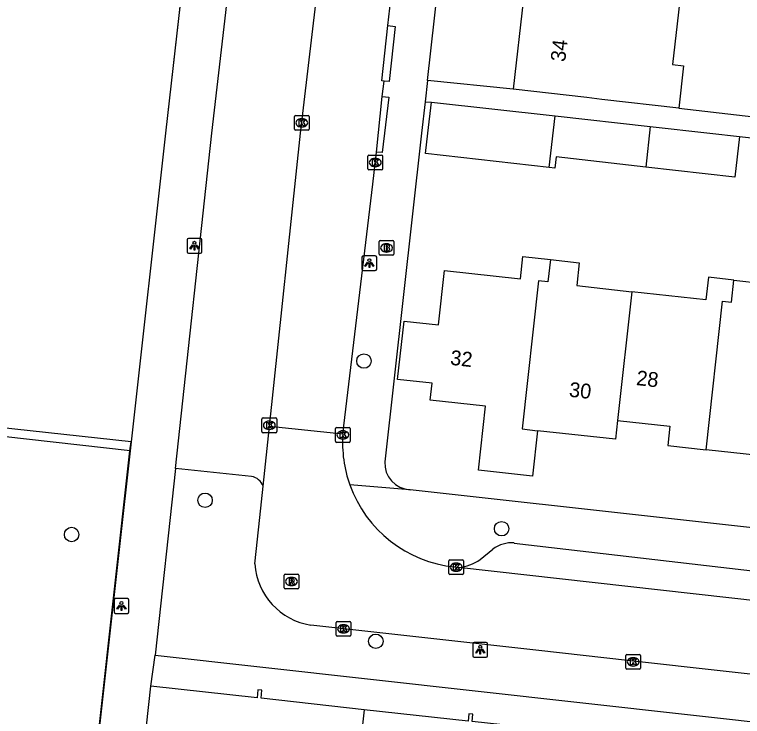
# Model space of a CAD drawing. Extents: x 162082 to 163393, y 388091 to 388632.
# Drawn here: x 162700.61 to 162749.8, y 388210.56 to 388258.01 of the extents above; entities that cross this region are included whole.
import ezdxf

# ---------------------------------------------------------------- set-up
doc = ezdxf.new("R2010")
doc.units = 0
for name, color, linetype in [('IMGEO_Boom', 7, 'Continuous'), ('IMGEO_Brandkraan', 7, 'Continuous'), ('IMGEO_Groenvoorziening', 7, 'Continuous'), ('IMGEO_Hek', 7, 'Continuous'), ('IMGEO_Kolk', 7, 'Continuous'), ('IMGEO_Lichtpunt', 7, 'Continuous'), ('IMGEO_Pand', 7, 'Continuous'), ('IMGEO_Pand_nummerreeks', 7, 'Continuous'), ('IMGEO_Rijbaan_lokaal_open', 7, 'Continuous'), ('IMGEO_Rioolput', 7, 'Continuous'), ('IMGEO_Voetpad_open', 7, 'Continuous')]:
    doc.layers.add(name, color=color, linetype=linetype)

msp = doc.modelspace()

# ---------------------------------------------------------------- linework, layer by layer
at = {"layer": 'IMGEO_Boom'}
for centre in [(162724.221, 388234.588), (162713.487, 388225.175), (162704.464, 388222.861), (162733.523, 388223.253), (162725.022, 388215.647)]:
    msp.add_circle(centre, 0.489, dxfattribs=at)
at = {"layer": 'IMGEO_Brandkraan'}
for p, q in [((162725.247, 388241.81), (162725.247, 388242.662)), ((162725.322, 388242.736), (162726.174, 388242.736)), ((162725.735, 388242.516), (162725.76, 388242.516)), ((162726.248, 388242.662), (162726.248, 388241.81)), ((162726.174, 388241.736), (162725.322, 388241.736)), ((162725.758, 388241.956), (162725.733, 388241.956))]:
    msp.add_line(p, q, dxfattribs=at)
for points in [[(162725.247, 388241.81), (162725.247, 388242.662)], [(162725.322, 388242.736), (162726.174, 388242.736)], [(162726.248, 388242.662), (162726.248, 388241.81)], [(162725.595, 388242.436), (162725.595, 388242.036), (162725.808, 388242.036)], [(162725.826, 388242.436), (162725.595, 388242.436)], [(162725.774, 388242.355), (162725.72, 388242.355), (162725.72, 388242.279)], [(162725.72, 388242.279), (162725.773, 388242.279)], [(162725.782, 388242.203), (162725.72, 388242.203), (162725.72, 388242.122)], [(162725.72, 388242.122), (162725.782, 388242.122)], [(162726.174, 388241.736), (162725.322, 388241.736)]]:
    msp.add_lwpolyline(points, dxfattribs=at)
for centre, radius, start, end in [((162725.324, 388242.66), 0.0765, 91.552, 178.448), ((162725.324, 388242.66), 0.0765, 91.552, 178.448), ((162726.172, 388242.66), 0.0765, 1.552, 88.448), ((162726.172, 388242.66), 0.0765, 1.552, 88.448), ((162725.775, 388242.317), 0.0379, 267.8285, 90.9355), ((162725.783, 388242.162), 0.0404, 269.8759, 90.5077), ((162725.814, 388242.287), 0.251, 268.6676, 293.5347), ((162725.83, 388242.291), 0.145, 59.4692, 91.5367), ((162725.855, 388242.338), 0.0922, 285.5137, 58.1501), ((162725.86, 388242.146), 0.105, 301.3115, 78.989), ((162725.324, 388241.812), 0.0765, 181.552, 268.448), ((162725.324, 388241.812), 0.0765, 181.552, 268.448), ((162726.172, 388241.812), 0.0765, 271.552, 358.448), ((162726.172, 388241.812), 0.0765, 271.552, 358.448)]:
    msp.add_arc(centre, radius, start, end, dxfattribs=at)
for centre, major_axis, ratio, start_param, end_param in [((162725.734, 388242.236), (-0.387, 0.002), 0.722429, 4.712389, 7.853982), ((162725.759, 388242.236), (-0.39, 0.002), 0.717154, 1.570796, 4.712389)]:
    msp.add_ellipse(centre, major_axis=major_axis, ratio=ratio, start_param=start_param, end_param=end_param, dxfattribs=at)
at = {"layer": 'IMGEO_Groenvoorziening'}
msp.add_lwpolyline([(162708.484, 388229.124), (162656.335, 388234.801), (162656.279, 388234.387)], dxfattribs=at)
at = {"layer": 'IMGEO_Hek'}
for points in [[(162714.001, 388278.243), (162710.804, 388250), (162708.484, 388229.124), (162704.239, 388190.917)], [(162708.417, 388228.516), (162663.577, 388233.565), (162656.279, 388234.387), (162655.072, 388234.523), (162654.187, 388234.622)]]:
    msp.add_lwpolyline(points, dxfattribs=at)
at = {"layer": 'IMGEO_Kolk'}
for p, q in [((162719.518, 388250.268), (162719.518, 388251.12)), ((162719.593, 388251.194), (162720.445, 388251.194)), ((162720.006, 388250.974), (162720.031, 388250.974)), ((162720.519, 388251.12), (162720.519, 388250.268)), ((162720.029, 388250.414), (162720.004, 388250.414)), ((162720.445, 388250.194), (162719.593, 388250.194)), ((162724.486, 388247.585), (162724.486, 388248.437)), ((162724.561, 388248.511), (162725.413, 388248.511)), ((162725.487, 388248.437), (162725.487, 388247.585)), ((162724.974, 388248.291), (162724.999, 388248.291)), ((162725.413, 388247.511), (162724.561, 388247.511)), ((162724.997, 388247.731), (162724.972, 388247.731)), ((162717.403, 388230.743), (162718.255, 388230.743)), ((162717.328, 388229.817), (162717.328, 388230.669)), ((162717.816, 388230.523), (162717.841, 388230.523)), ((162718.329, 388230.669), (162718.329, 388229.817)), ((162718.255, 388229.743), (162717.403, 388229.743)), ((162717.839, 388229.963), (162717.814, 388229.963)), ((162722.295, 388229.166), (162722.295, 388230.018)), ((162722.37, 388230.092), (162723.222, 388230.092)), ((162722.783, 388229.872), (162722.808, 388229.872)), ((162723.296, 388230.018), (162723.296, 388229.166)), ((162722.806, 388229.312), (162722.781, 388229.312)), ((162723.222, 388229.092), (162722.37, 388229.092)), ((162729.958, 388220.229), (162729.958, 388221.081)), ((162730.033, 388221.155), (162730.885, 388221.155)), ((162730.446, 388220.935), (162730.471, 388220.935)), ((162730.959, 388221.081), (162730.959, 388220.229)), ((162730.469, 388220.375), (162730.444, 388220.375)), ((162730.885, 388220.155), (162730.033, 388220.155)), ((162722.345, 388216.061), (162722.345, 388216.913)), ((162722.42, 388216.987), (162723.272, 388216.987)), ((162723.346, 388216.913), (162723.346, 388216.061)), ((162722.833, 388216.767), (162722.858, 388216.767)), ((162723.272, 388215.987), (162722.42, 388215.987)), ((162722.856, 388216.207), (162722.831, 388216.207)), ((162741.917, 388213.824), (162741.917, 388214.676)), ((162741.992, 388214.75), (162742.844, 388214.75)), ((162742.405, 388214.53), (162742.43, 388214.53)), ((162742.918, 388214.676), (162742.918, 388213.824)), ((162742.428, 388213.97), (162742.403, 388213.97)), ((162742.844, 388213.75), (162741.992, 388213.75))]:
    msp.add_line(p, q, dxfattribs=at)
for points in [[(162719.518, 388250.268), (162719.518, 388251.12)], [(162719.593, 388251.194), (162720.445, 388251.194)], [(162719.839, 388250.894), (162719.962, 388250.894), (162719.962, 388250.743), (162720.092, 388250.894), (162720.256, 388250.894), (162720.11, 388250.743), (162720.263, 388250.494), (162720.111, 388250.494), (162720.026, 388250.658), (162719.962, 388250.591), (162719.962, 388250.494), (162719.839, 388250.494), (162719.839, 388250.894)], [(162720.519, 388251.12), (162720.519, 388250.268)], [(162720.445, 388250.194), (162719.593, 388250.194)], [(162724.486, 388247.585), (162724.486, 388248.437)], [(162724.561, 388248.511), (162725.413, 388248.511)], [(162725.487, 388248.437), (162725.487, 388247.585)], [(162724.807, 388248.211), (162724.93, 388248.211), (162724.93, 388248.06), (162725.06, 388248.211), (162725.224, 388248.211), (162725.078, 388248.06), (162725.231, 388247.811), (162725.079, 388247.811), (162724.994, 388247.975), (162724.93, 388247.908), (162724.93, 388247.811), (162724.807, 388247.811), (162724.807, 388248.211)], [(162725.413, 388247.511), (162724.561, 388247.511)], [(162717.403, 388230.743), (162718.255, 388230.743)], [(162717.328, 388229.817), (162717.328, 388230.669)], [(162717.649, 388230.443), (162717.772, 388230.443), (162717.772, 388230.292), (162717.902, 388230.443), (162718.066, 388230.443), (162717.92, 388230.292), (162718.073, 388230.043), (162717.921, 388230.043), (162717.836, 388230.207), (162717.772, 388230.14), (162717.772, 388230.043), (162717.649, 388230.043), (162717.649, 388230.443)], [(162718.329, 388230.669), (162718.329, 388229.817)], [(162718.255, 388229.743), (162717.403, 388229.743)], [(162722.295, 388229.166), (162722.295, 388230.018)], [(162722.37, 388230.092), (162723.222, 388230.092)], [(162722.616, 388229.792), (162722.739, 388229.792), (162722.739, 388229.641), (162722.869, 388229.792), (162723.033, 388229.792), (162722.887, 388229.641), (162723.04, 388229.392), (162722.888, 388229.392), (162722.803, 388229.556), (162722.739, 388229.489), (162722.739, 388229.392), (162722.616, 388229.392), (162722.616, 388229.792)], [(162723.296, 388230.018), (162723.296, 388229.166)], [(162723.222, 388229.092), (162722.37, 388229.092)], [(162729.958, 388220.229), (162729.958, 388221.081)], [(162730.033, 388221.155), (162730.885, 388221.155)], [(162730.279, 388220.855), (162730.402, 388220.855), (162730.402, 388220.704), (162730.532, 388220.855), (162730.696, 388220.855), (162730.55, 388220.704), (162730.703, 388220.455), (162730.551, 388220.455), (162730.466, 388220.619), (162730.402, 388220.552), (162730.402, 388220.455), (162730.279, 388220.455), (162730.279, 388220.855)], [(162730.959, 388221.081), (162730.959, 388220.229)], [(162730.885, 388220.155), (162730.033, 388220.155)], [(162722.345, 388216.061), (162722.345, 388216.913)], [(162722.42, 388216.987), (162723.272, 388216.987)], [(162723.346, 388216.913), (162723.346, 388216.061)], [(162722.666, 388216.687), (162722.789, 388216.687), (162722.789, 388216.536), (162722.919, 388216.687), (162723.083, 388216.687), (162722.937, 388216.536), (162723.09, 388216.287), (162722.938, 388216.287), (162722.853, 388216.451), (162722.789, 388216.384), (162722.789, 388216.287), (162722.666, 388216.287), (162722.666, 388216.687)], [(162723.272, 388215.987), (162722.42, 388215.987)], [(162741.917, 388213.824), (162741.917, 388214.676)], [(162741.992, 388214.75), (162742.844, 388214.75)], [(162742.238, 388214.45), (162742.361, 388214.45), (162742.361, 388214.299), (162742.491, 388214.45), (162742.655, 388214.45), (162742.509, 388214.299), (162742.662, 388214.05), (162742.51, 388214.05), (162742.425, 388214.214), (162742.361, 388214.147), (162742.361, 388214.05), (162742.238, 388214.05), (162742.238, 388214.45)], [(162742.918, 388214.676), (162742.918, 388213.824)], [(162742.844, 388213.75), (162741.992, 388213.75)]]:
    msp.add_lwpolyline(points, dxfattribs=at)
for centre, start, end in [((162719.595, 388251.118), 91.552, 178.448), ((162719.595, 388251.118), 91.552, 178.448), ((162720.443, 388251.118), 1.552, 88.448), ((162720.443, 388251.118), 1.552, 88.448), ((162719.595, 388250.27), 181.552, 268.448), ((162719.595, 388250.27), 181.552, 268.448), ((162720.443, 388250.27), 271.552, 358.448), ((162720.443, 388250.27), 271.552, 358.448), ((162724.563, 388248.435), 91.552, 178.448), ((162724.563, 388248.435), 91.552, 178.448), ((162725.411, 388248.435), 1.552, 88.448), ((162725.411, 388248.435), 1.552, 88.448), ((162724.563, 388247.587), 181.552, 268.448), ((162724.563, 388247.587), 181.552, 268.448), ((162725.411, 388247.587), 271.552, 358.448), ((162725.411, 388247.587), 271.552, 358.448), ((162717.405, 388230.667), 91.552, 178.448), ((162717.405, 388230.667), 91.552, 178.448), ((162718.253, 388230.667), 1.552, 88.448), ((162718.253, 388230.667), 1.552, 88.448), ((162717.405, 388229.819), 181.552, 268.448), ((162717.405, 388229.819), 181.552, 268.448), ((162718.253, 388229.819), 271.552, 358.448), ((162718.253, 388229.819), 271.552, 358.448), ((162722.372, 388230.016), 91.552, 178.448), ((162722.372, 388230.016), 91.552, 178.448), ((162723.22, 388230.016), 1.552, 88.448), ((162723.22, 388230.016), 1.552, 88.448), ((162722.372, 388229.168), 181.552, 268.448), ((162722.372, 388229.168), 181.552, 268.448), ((162723.22, 388229.168), 271.552, 358.448), ((162723.22, 388229.168), 271.552, 358.448), ((162730.035, 388221.079), 91.552, 178.448), ((162730.035, 388221.079), 91.552, 178.448), ((162730.883, 388221.079), 1.552, 88.448), ((162730.883, 388221.079), 1.552, 88.448), ((162730.035, 388220.231), 181.552, 268.448), ((162730.035, 388220.231), 181.552, 268.448), ((162730.883, 388220.231), 271.552, 358.448), ((162730.883, 388220.231), 271.552, 358.448), ((162722.422, 388216.911), 91.552, 178.448), ((162722.422, 388216.911), 91.552, 178.448), ((162723.27, 388216.911), 1.552, 88.448), ((162723.27, 388216.911), 1.552, 88.448), ((162722.422, 388216.063), 181.552, 268.448), ((162722.422, 388216.063), 181.552, 268.448), ((162723.27, 388216.063), 271.552, 358.448), ((162723.27, 388216.063), 271.552, 358.448), ((162741.994, 388214.674), 91.552, 178.448), ((162741.994, 388214.674), 91.552, 178.448), ((162742.842, 388214.674), 1.552, 88.448), ((162742.842, 388214.674), 1.552, 88.448), ((162741.994, 388213.826), 181.552, 268.448), ((162741.994, 388213.826), 181.552, 268.448), ((162742.842, 388213.826), 271.552, 358.448), ((162742.842, 388213.826), 271.552, 358.448)]:
    msp.add_arc(centre, 0.0765, start, end, dxfattribs=at)
for centre, major_axis, ratio, start_param, end_param in [((162720.005, 388250.694), (-0.387, 0.002), 0.722429, 4.712389, 7.853982), ((162720.03, 388250.694), (-0.39, 0.002), 0.717154, 1.570796, 4.712389), ((162724.973, 388248.011), (-0.387, 0.002), 0.722429, 4.712389, 7.853982), ((162724.998, 388248.011), (-0.39, 0.002), 0.717154, 1.570796, 4.712389), ((162717.815, 388230.243), (-0.387, 0.002), 0.722429, 4.712389, 7.853982), ((162717.84, 388230.243), (-0.39, 0.002), 0.717154, 1.570796, 4.712389), ((162722.782, 388229.592), (-0.387, 0.002), 0.722429, 4.712389, 7.853982), ((162722.807, 388229.592), (-0.39, 0.002), 0.717154, 1.570796, 4.712389), ((162730.445, 388220.655), (-0.387, 0.002), 0.722429, 4.712389, 7.853982), ((162730.47, 388220.655), (-0.39, 0.002), 0.717154, 1.570796, 4.712389), ((162722.832, 388216.487), (-0.387, 0.002), 0.722429, 4.712389, 7.853982), ((162722.857, 388216.487), (-0.39, 0.002), 0.717154, 1.570796, 4.712389), ((162742.404, 388214.25), (-0.387, 0.002), 0.722429, 4.712389, 7.853982), ((162742.429, 388214.25), (-0.39, 0.002), 0.717154, 1.570796, 4.712389)]:
    msp.add_ellipse(centre, major_axis=major_axis, ratio=ratio, start_param=start_param, end_param=end_param, dxfattribs=at)
at = {"layer": 'IMGEO_Lichtpunt'}
for p, q in [((162712.266, 388242.789), (162712.266, 388241.982)), ((162712.266, 388242.789), (162712.266, 388241.982)), ((162713.168, 388242.884), (162712.36, 388242.884)), ((162713.168, 388242.884), (162712.36, 388242.884)), ((162713.262, 388241.982), (162713.262, 388242.789)), ((162713.262, 388241.982), (162713.262, 388242.789)), ((162712.36, 388241.888), (162713.168, 388241.888)), ((162712.36, 388241.888), (162713.168, 388241.888)), ((162724.088, 388241.609), (162724.088, 388240.802)), ((162724.088, 388241.609), (162724.088, 388240.802)), ((162724.99, 388241.704), (162724.182, 388241.704)), ((162724.99, 388241.704), (162724.182, 388241.704)), ((162725.084, 388240.802), (162725.084, 388241.609)), ((162725.084, 388240.802), (162725.084, 388241.609)), ((162724.182, 388240.708), (162724.99, 388240.708)), ((162724.182, 388240.708), (162724.99, 388240.708)), ((162707.335, 388218.432), (162707.335, 388217.625)), ((162707.335, 388218.432), (162707.335, 388217.625)), ((162708.237, 388218.527), (162707.429, 388218.527)), ((162708.237, 388218.527), (162707.429, 388218.527)), ((162708.331, 388217.625), (162708.331, 388218.432)), ((162708.331, 388217.625), (162708.331, 388218.432)), ((162707.429, 388217.531), (162708.237, 388217.531)), ((162707.429, 388217.531), (162708.237, 388217.531)), ((162731.585, 388215.473), (162731.585, 388214.666)), ((162731.585, 388215.473), (162731.585, 388214.666)), ((162732.487, 388215.568), (162731.679, 388215.568)), ((162732.487, 388215.568), (162731.679, 388215.568)), ((162732.581, 388214.666), (162732.581, 388215.473)), ((162732.581, 388214.666), (162732.581, 388215.473)), ((162731.679, 388214.572), (162732.487, 388214.572)), ((162731.679, 388214.572), (162732.487, 388214.572))]:
    msp.add_line(p, q, dxfattribs=at)
for points in [[(162712.64, 388242.453), (162712.679, 388242.425), (162712.491, 388242.163), (162712.453, 388242.19), (162712.64, 388242.453)], [(162712.742, 388242.405), (162712.789, 388242.405), (162712.789, 388242.083), (162712.742, 388242.083), (162712.742, 388242.405)], [(162712.852, 388242.425), (162712.89, 388242.452), (162713.077, 388242.19), (162713.038, 388242.162), (162712.852, 388242.425)], [(162724.462, 388241.273), (162724.501, 388241.245), (162724.313, 388240.983), (162724.275, 388241.01), (162724.462, 388241.273)], [(162724.564, 388241.225), (162724.611, 388241.225), (162724.611, 388240.903), (162724.564, 388240.903), (162724.564, 388241.225)], [(162724.674, 388241.245), (162724.712, 388241.272), (162724.899, 388241.01), (162724.86, 388240.982), (162724.674, 388241.245)], [(162707.709, 388218.096), (162707.748, 388218.068), (162707.56, 388217.806), (162707.522, 388217.833), (162707.709, 388218.096)], [(162707.811, 388218.048), (162707.858, 388218.048), (162707.858, 388217.726), (162707.811, 388217.726), (162707.811, 388218.048)], [(162707.921, 388218.068), (162707.959, 388218.095), (162708.146, 388217.833), (162708.107, 388217.805), (162707.921, 388218.068)], [(162731.959, 388215.137), (162731.998, 388215.109), (162731.81, 388214.847), (162731.772, 388214.874), (162731.959, 388215.137)], [(162732.061, 388215.089), (162732.108, 388215.089), (162732.108, 388214.767), (162732.061, 388214.767), (162732.061, 388215.089)], [(162732.171, 388215.109), (162732.209, 388215.136), (162732.396, 388214.874), (162732.357, 388214.846), (162732.171, 388215.109)]]:
    msp.add_lwpolyline(points, dxfattribs=at)
for centre in [(162712.765, 388242.587), (162724.587, 388241.407), (162707.834, 388218.23), (162732.084, 388215.271)]:
    msp.add_circle(centre, 0.0994, dxfattribs=at)
for centre, start, end in [((162712.36, 388242.789), 90, 180), ((162712.36, 388242.789), 90, 180), ((162713.168, 388242.789), 0, 90), ((162713.168, 388242.789), 0, 90), ((162712.36, 388241.982), 180, 270), ((162712.36, 388241.982), 180, 270), ((162713.168, 388241.982), 270, 0), ((162713.168, 388241.982), 270, 360), ((162724.182, 388241.609), 90, 180), ((162724.182, 388241.609), 90, 180), ((162724.99, 388241.609), 0, 90), ((162724.99, 388241.609), 0, 90), ((162724.182, 388240.802), 180, 270), ((162724.182, 388240.802), 180, 270), ((162724.99, 388240.802), 270, 0), ((162724.99, 388240.802), 270, 360), ((162707.429, 388218.432), 90, 180), ((162707.429, 388218.432), 90, 180), ((162708.237, 388218.432), 0, 90), ((162708.237, 388218.432), 0, 90), ((162707.429, 388217.625), 180, 270), ((162707.429, 388217.625), 180, 270), ((162708.237, 388217.625), 270, 0), ((162708.237, 388217.625), 270, 360), ((162731.679, 388215.473), 90, 180), ((162731.679, 388215.473), 90, 180), ((162732.487, 388215.473), 0, 90), ((162732.487, 388215.473), 0, 90), ((162731.679, 388214.666), 180, 270), ((162731.679, 388214.666), 180, 270), ((162732.487, 388214.666), 270, 0), ((162732.487, 388214.666), 270, 360)]:
    msp.add_arc(centre, 0.0946, start, end, dxfattribs=at)
at = {"layer": 'IMGEO_Pand'}
for points in [[(162745.791, 388260.953), (162745.073, 388254.64), (162745.818, 388254.555), (162745.492, 388251.69)], [(162735.012, 388259.116), (162734.312, 388252.961)], [(162745.492, 388251.69), (162740.3, 388252.28), (162739.28, 388252.396), (162734.312, 388252.961)], [(162736.743, 388247.669), (162728.384, 388248.621), (162728.541, 388250), (162728.778, 388252.082)], [(162728.778, 388252.082), (162737.151, 388251.155)], [(162736.743, 388247.669), (162737.151, 388251.155)], [(162737.151, 388251.155), (162743.566, 388250.445)], [(162743.566, 388250.445), (162743.263, 388247.704)], [(162743.566, 388250.445), (162747.586, 388250), (162749.612, 388249.776)], [(162749.612, 388249.776), (162749.283, 388247.018), (162743.263, 388247.704)], [(162743.263, 388247.704), (162737.219, 388248.392), (162737.131, 388247.625), (162736.743, 388247.669)], [(162735.956, 388229.882), (162735.616, 388226.798), (162731.956, 388227.202), (162732.435, 388231.539), (162728.697, 388231.952), (162728.823, 388233.089), (162726.496, 388233.346), (162726.931, 388237.286), (162729.258, 388237.029), (162729.666, 388240.719), (162734.802, 388240.152), (162734.967, 388241.649), (162736.823, 388241.444)], [(162736.823, 388241.444), (162736.656, 388239.94), (162736.029, 388240.012), (162734.918, 388229.997), (162735.956, 388229.882)], [(162736.823, 388241.444), (162738.771, 388241.229), (162738.601, 388239.691), (162742.33, 388239.279)], [(162749.218, 388240.061), (162747.501, 388240.25), (162747.333, 388238.726), (162742.33, 388239.279)], [(162747.345, 388228.591), (162748.458, 388238.633), (162749.052, 388238.567), (162749.218, 388240.061)], [(162749.218, 388240.061), (162751.227, 388239.839), (162751.053, 388238.265), (162754.694, 388237.863)], [(162742.33, 388239.279), (162741.366, 388230.57)], [(162741.366, 388230.57), (162741.226, 388229.3), (162735.956, 388229.882)], [(162741.366, 388230.57), (162744.9, 388230.18), (162744.756, 388228.877), (162747.345, 388228.591)], [(162753.728, 388229.16), (162753.589, 388227.901), (162747.345, 388228.591)], [(162708.768, 388202.91), (162709.83, 388212.61)], [(162724.237, 388211.019), (162717.271, 388211.798), (162717.33, 388212.333), (162717.055, 388212.363), (162716.996, 388211.825), (162709.83, 388212.61)], [(162724.237, 388211.019), (162722.353, 388193.838)], [(162738.585, 388209.46), (162731.531, 388210.232), (162731.584, 388210.712), (162731.317, 388210.742), (162731.262, 388210.233), (162724.237, 388211.019)]]:
    msp.add_lwpolyline(points, dxfattribs=at)
at = {"layer": 'IMGEO_Rijbaan_lokaal_open'}
for points in [[(162717.833, 388230.157), (162719.945, 388250), (162723.544, 388280.513)], [(162725.847, 388257.264), (162726.114, 388259.643)], [(162725.592, 388253.516), (162725.429, 388253.533), (162725.847, 388257.264)], [(162725.455, 388252.469), (162725.592, 388253.516)], [(162725.081, 388248.711), (162725.455, 388252.469)], [(162722.798, 388229.646), (162724.831, 388246.551), (162725.081, 388248.711)], [(162717.405, 388226.137), (162717.833, 388230.157)], [(162722.798, 388229.646), (162717.833, 388230.157)], [(162716.844, 388220.869), (162717.178, 388224.004), (162717.405, 388226.137)], [(162730.35, 388220.666), (162730.619, 388220.635)], [(162755.71, 388217.817), (162730.619, 388220.635)], [(162755.166, 388212.869), (162742.036, 388214.341), (162736.049, 388215.013), (162720.64, 388216.741)]]:
    msp.add_lwpolyline(points, dxfattribs=at)
for centre, radius, start, end in [((162731.185, 388229.043), 8.408, 175.8879, 199.69), ((162731.198, 388229.044), 8.421, 199.6679, 264.2223), ((162721.312, 388221.168), 4.478, 183.8332, 261.3685)]:
    msp.add_arc(centre, radius, start, end, dxfattribs=at)
at = {"layer": 'IMGEO_Rioolput'}
for p, q in [((162718.823, 388219.261), (162718.823, 388220.113)), ((162718.898, 388220.187), (162719.75, 388220.187)), ((162719.311, 388219.967), (162719.336, 388219.967)), ((162719.824, 388220.113), (162719.824, 388219.261)), ((162719.334, 388219.407), (162719.309, 388219.407)), ((162719.75, 388219.187), (162718.898, 388219.187))]:
    msp.add_line(p, q, dxfattribs=at)
for points in [[(162718.823, 388219.261), (162718.823, 388220.113)], [(162718.898, 388220.187), (162719.75, 388220.187)], [(162719.412, 388219.885), (162719.16, 388219.887), (162719.16, 388219.487)], [(162719.824, 388220.113), (162719.824, 388219.261)], [(162719.16, 388219.487), (162719.284, 388219.487), (162719.284, 388219.649), (162719.295, 388219.649)], [(162719.338, 388219.806), (162719.284, 388219.806), (162719.284, 388219.725)], [(162719.284, 388219.725), (162719.336, 388219.725)], [(162719.342, 388219.62), (162719.413, 388219.487), (162719.553, 388219.487), (162719.488, 388219.613)], [(162719.75, 388219.187), (162718.898, 388219.187)]]:
    msp.add_lwpolyline(points, dxfattribs=at)
for centre, radius, start, end in [((162718.9, 388220.111), 0.0765, 91.552, 178.448), ((162718.9, 388220.111), 0.0765, 91.552, 178.448), ((162719.411, 388219.775), 0.109, 350.3612, 89.416), ((162719.748, 388220.111), 0.0765, 1.552, 88.448), ((162719.748, 388220.111), 0.0765, 1.552, 88.448), ((162719.294, 388219.596), 0.0533, 26.0293, 88.6989), ((162719.32, 388219.914), 0.19, 274.7715, 282.9687), ((162719.344, 388219.71), 0.0964, 77.0061, 93.1865), ((162719.358, 388219.767), 0.0378, 276.6634, 79.6772), ((162719.409, 388219.775), 0.112, 277.5842, 350.9817), ((162719.393, 388219.56), 0.108, 29.5134, 73.7905), ((162718.9, 388219.263), 0.0765, 181.552, 268.448), ((162718.9, 388219.263), 0.0765, 181.552, 268.448), ((162719.748, 388219.263), 0.0765, 271.552, 358.448), ((162719.748, 388219.263), 0.0765, 271.552, 358.448)]:
    msp.add_arc(centre, radius, start, end, dxfattribs=at)
for centre, major_axis, ratio, start_param, end_param in [((162719.31, 388219.687), (-0.387, 0.002), 0.722429, 4.712389, 7.853982), ((162719.335, 388219.687), (-0.39, 0.002), 0.717154, 1.570796, 4.712389)]:
    msp.add_ellipse(centre, major_axis=major_axis, ratio=ratio, start_param=start_param, end_param=end_param, dxfattribs=at)
at = {"layer": 'IMGEO_Voetpad_open'}
for points in [[(162719.528, 388326.805), (162714.003, 388278.163), (162713.987, 388278.025), (162710.804, 388250), (162708.484, 388229.124)], [(162728.52, 388253.553), (162735.64, 388316.989)], [(162745.492, 388251.69), (162755.049, 388250.59), (162763.343, 388313.856), (162751.954, 388315.151)], [(162711.489, 388227.332), (162713.938, 388250), (162717.461, 388280.321), (162722.517, 388279.851)], [(162725.847, 388257.264), (162726.332, 388257.212), (162725.917, 388253.481), (162725.592, 388253.516)], [(162728.52, 388253.553), (162728.359, 388252.123)], [(162734.312, 388252.961), (162728.52, 388253.553)], [(162725.455, 388252.469), (162725.91, 388252.418), (162725.458, 388248.677), (162725.081, 388248.711)], [(162728.359, 388252.123), (162728.121, 388250), (162725.626, 388227.777)], [(162728.359, 388252.123), (162728.778, 388252.082)], [(162749.612, 388249.776), (162751.238, 388249.597)], [(162704.239, 388190.913), (162708.41, 388228.518), (162708.484, 388229.124)], [(162711.489, 388227.332), (162710.107, 388214.707)], [(162716.629, 388226.782), (162711.489, 388227.332)], [(162727.336, 388225.893), (162727.328, 388225.872), (162723.268, 388226.21)], [(162780.519, 388219.969), (162727.336, 388225.893)], [(162732.084, 388221.166), (162732.942, 388221.867)], [(162734.38, 388222.288), (162772.391, 388217.862)], [(162709.83, 388212.61), (162710.107, 388214.707)], [(162710.107, 388214.707), (162767.722, 388208.275)]]:
    msp.add_lwpolyline(points, dxfattribs=at)
for centre, radius, start, end in [((162727.424, 388227.691), 1.8, 177.2469, 267.2096), ((162716.469, 388225.8), 0.995, 19.8025, 80.7318), ((162734.183, 388220.295), 2.003, 84.3516, 128.2851), ((162730.232, 388223.989), 3.377, 276.5829, 303.2639)]:
    msp.add_arc(centre, radius, start, end, dxfattribs=at)

# ---------------------------------------------------------------- texts
at = {"layer": 'IMGEO_Pand_nummerreeks'}
for s, rotation, p in [('34', 83.5118, (162737.821, 388254.787)), ('32', 353.6975, (162730.018, 388234.342)), ('28', 353.7025, (162742.591, 388232.97)), ('30', 353.698, (162738.049, 388232.185))]:
    msp.add_text(s, height=1, rotation=rotation, dxfattribs=at).set_placement(p)

doc.saveas('drawing.dxf')
